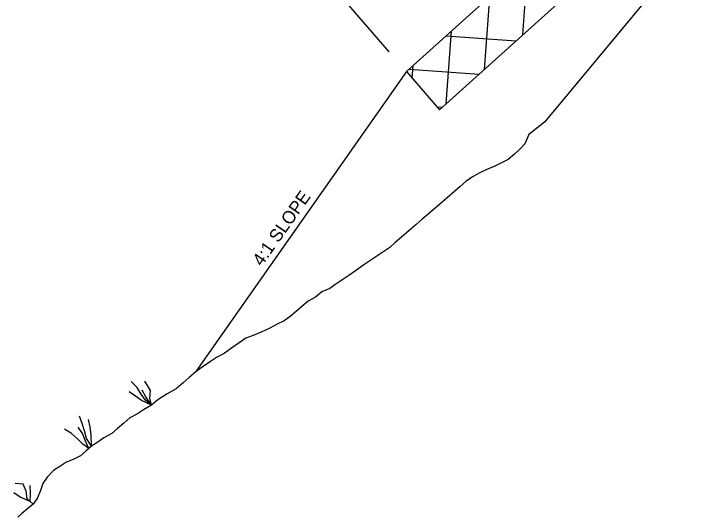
# Model space of a CAD drawing. Extents: x 192699 to 285914, y 194342 to 233219.
# Drawn here: x 262749.07 to 262768.34, y 213649.37 to 213663.47 of the extents above; entities that cross this region are included whole.
import ezdxf

# ---------------------------------------------------------------- set-up
doc = ezdxf.new("R2010")
doc.units = 0
doc.layers.add('TYPICAL SECTION FOR MOT', color=7, linetype='Continuous')

msp = doc.modelspace()

# ---------------------------------------------------------------- linework, layer by layer
at = {"layer": 'TYPICAL SECTION FOR MOT'}
for p, q in [((262783.836, 213683.281), (262760.061, 213661.852)), ((262784.763, 213682.21), (262760.988, 213660.781)), ((262779.456, 213679.172), (262763.929, 213660.44)), ((262759.577, 213662.411), (262754.673, 213668.076)), ((262763.32, 213662.883), (262763.467, 213664.922)), ((262762.248, 213661.917), (262762.395, 213663.956)), ((262761.176, 213660.95), (262761.323, 213662.989)), ((262761.172, 213662.853), (262763.131, 213662.712)), ((262760.061, 213661.852), (262754.161, 213653.451)), ((262760.061, 213661.852), (262760.988, 213660.781)), ((262760.142, 213661.925), (262762.101, 213661.784)), ((262760.225, 213661.664), (262760.25, 213662.023)), ((262760.914, 213660.867), (262761.071, 213660.856))]:
    msp.add_line(p, q, dxfattribs=at)
for points in [[(262763.929, 213660.44), (262763.486, 213660.096), (262763.376, 213659.832), (262763.238, 213659.678), (262763.083, 213659.544), (262762.909, 213659.394), (262762.721, 213659.298), (262762.533, 213659.203), (262762.308, 213659.11), (262762.12, 213659.015), (262761.912, 213658.903), (262761.722, 213658.772), (262761.567, 213658.638), (262761.412, 213658.504), (262761.199, 213658.319), (262760.986, 213658.135), (262760.812, 213657.984), (262760.657, 213657.85), (262760.503, 213657.716), (262760.329, 213657.566), (262760.135, 213657.398), (262759.922, 213657.214), (262759.748, 213657.063), (262759.593, 213656.929), (262759.402, 213656.798), (262759.231, 213656.683), (262759.04, 213656.552), (262758.869, 213656.437), (262758.639, 213656.272), (262758.448, 213656.141), (262758.277, 213656.026), (262758.086, 213655.895), (262757.914, 213655.78), (262757.69, 213655.687), (262757.516, 213655.537), (262757.308, 213655.425), (262757.134, 213655.274), (262756.979, 213655.14), (262756.805, 213654.989), (262756.633, 213654.874), (262756.445, 213654.779), (262756.238, 213654.667), (262755.994, 213654.558), (262755.769, 213654.465), (262755.564, 213654.389), (262755.374, 213654.258), (262755.163, 213654.109), (262754.953, 213653.961), (262754.745, 213653.849), (262754.574, 213653.735), (262754.344, 213653.57), (262754.173, 213653.455), (262753.979, 213653.288), (262753.805, 213653.137), (262753.612, 213652.969), (262753.365, 213652.824), (262753.1, 213652.661), (262752.926, 213652.511), (262752.699, 213652.382), (262752.527, 213652.267), (262752.319, 213652.155), (262752.145, 213652.004), (262751.971, 213651.854), (262751.816, 213651.72), (262751.589, 213651.591), (262751.418, 213651.476), (262751.246, 213651.362), (262751.092, 213651.228), (262750.937, 213651.094), (262750.749, 213650.998), (262750.524, 213650.906), (262750.353, 213650.791), (262750.181, 213650.676), (262750.004, 213650.489), (262749.883, 213650.317), (262749.815, 213650.122), (262749.727, 213649.911), (262749.606, 213649.738), (262749.451, 213649.604), (262749.296, 213649.47), (262749.18, 213649.37)], [(262752.926, 213652.511), (262752.754, 213652.65), (262752.63, 213652.813), (262752.517, 213653.003), (262752.356, 213653.168)], [(262752.926, 213652.511), (262752.876, 213652.705), (262752.892, 213652.921), (262752.738, 213653.177)], [(262752.926, 213652.511), (262752.645, 213652.64), (262752.472, 213652.761), (262752.299, 213652.882)], [(262752.926, 213652.511), (262752.761, 213652.74), (262752.665, 213652.929)], [(262751.246, 213651.362), (262751.098, 213651.572), (262751.042, 213651.794), (262750.984, 213651.997), (262750.908, 213652.202)], [(262751.246, 213651.362), (262751.232, 213651.671), (262751.203, 213651.9), (262751.155, 213652.112)], [(262751.169, 213651.295), (262750.996, 213651.416), (262750.853, 213651.562), (262750.683, 213651.72), (262750.482, 213651.834)], [(262751.169, 213651.295), (262751.075, 213651.501), (262750.991, 213651.716), (262750.868, 213651.897)], [(262749.606, 213649.738), (262749.444, 213649.886), (262749.414, 213650.097), (262749.328, 213650.293), (262749.103, 213650.318)], [(262749.525, 213649.812), (262749.536, 213650.033), (262749.525, 213650.261)], [(262749.525, 213649.812), (262749.248, 213649.936), (262749.066, 213650.049)]]:
    msp.add_lwpolyline(points, dxfattribs=at)

# ---------------------------------------------------------------- texts
msp.add_text('4:1 SLOPE', height=0.36, rotation=54.9195, dxfattribs=at).set_placement((262756.013, 213656.38))

doc.saveas('drawing.dxf')
